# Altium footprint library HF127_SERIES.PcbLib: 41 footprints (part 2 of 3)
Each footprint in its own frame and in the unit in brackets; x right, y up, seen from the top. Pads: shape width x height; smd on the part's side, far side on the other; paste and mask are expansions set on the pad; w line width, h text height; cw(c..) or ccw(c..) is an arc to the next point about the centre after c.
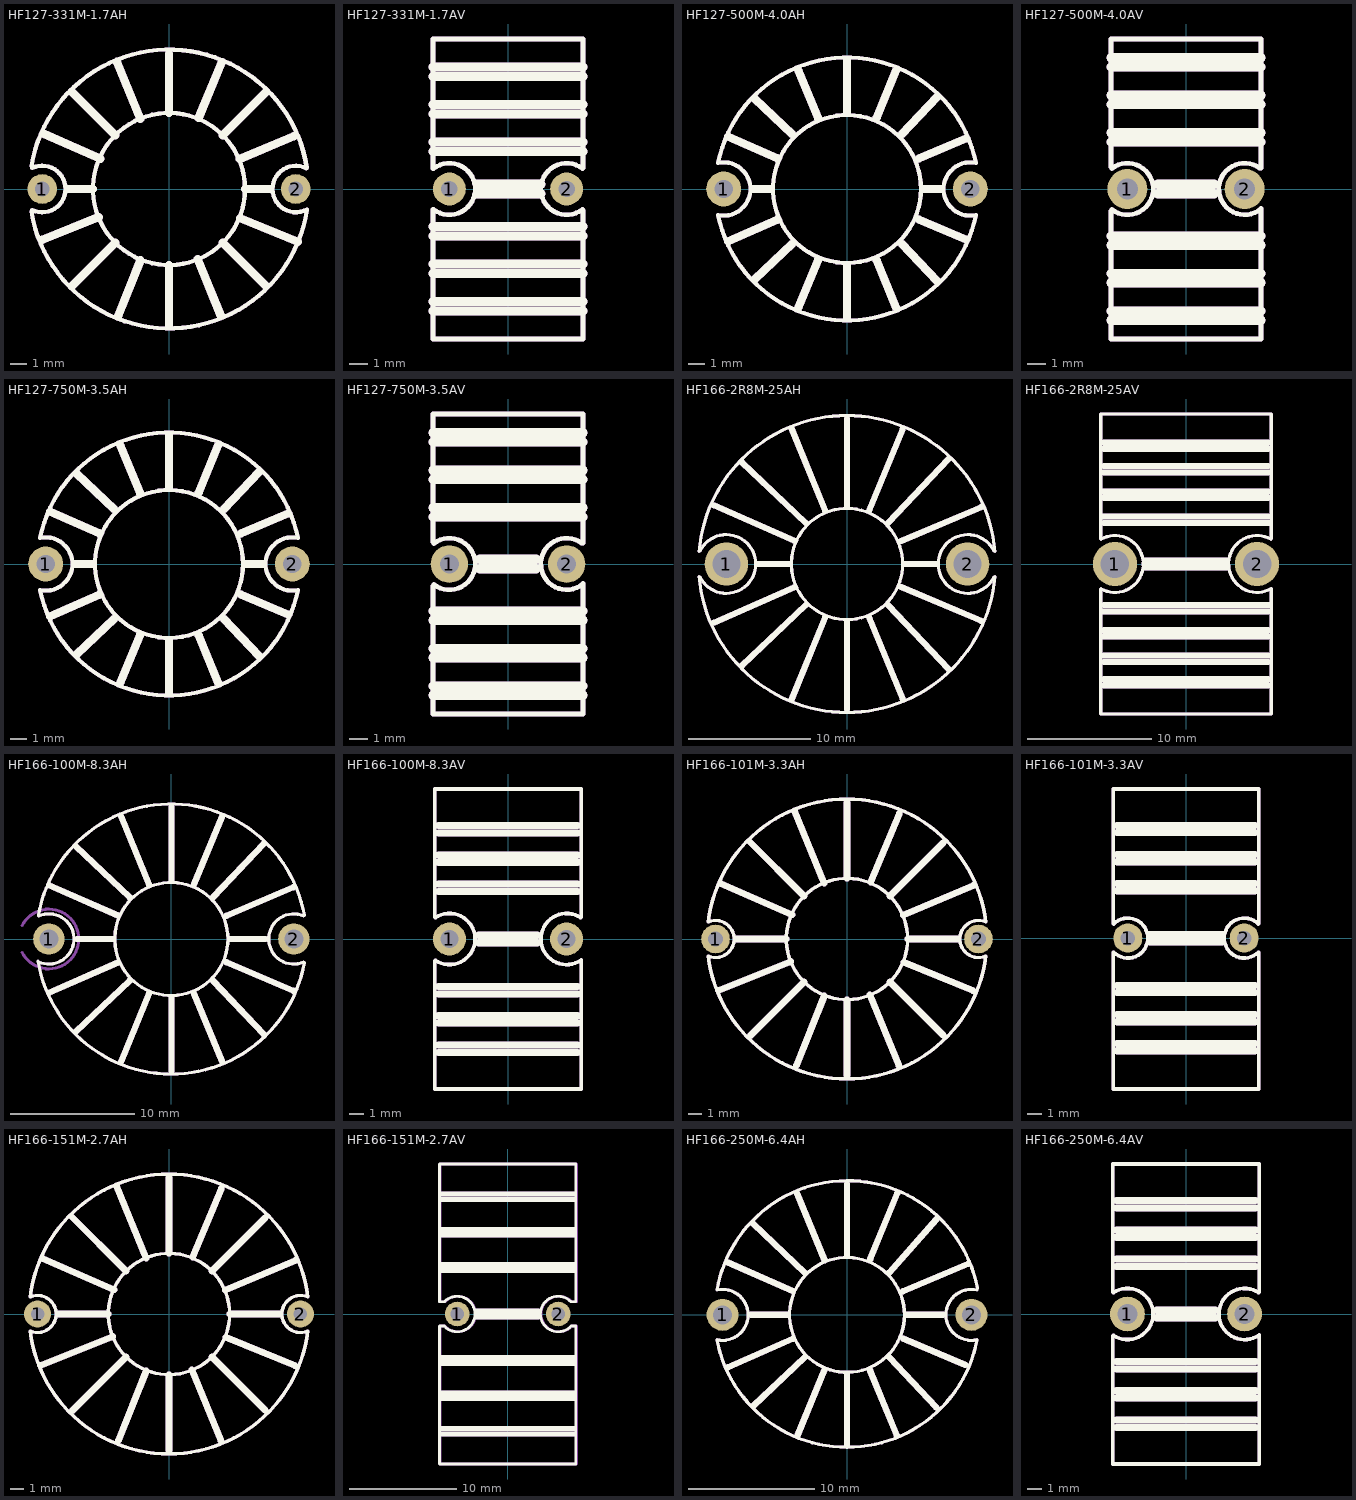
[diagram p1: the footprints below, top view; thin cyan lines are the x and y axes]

## HF127-331M-1.7AH [mil]
pads (2):
  round 70 hole 35: 1(-300,0) 2(300,0)
Top Overlay:
  circle w10: c0,0 r180
  lines w10: -325.63,-53.53 ccw(c0,0) 326.34,-49.02 ; -325.61,53.66 cw(c0,0) 326.16,50.18 ; -323.75,-49.61 ccw(c-300,0) -323.69,49.64 ; 324.6,49.19 ccw(c300,0) 326.03,-48.45
  lines w19.68: -300,-120 -166.38,-66.55 ; -295,130 -162.15,71.46 ; -240,0 -180,0 ; -230,-230 -127.5,-127.5 ; -230,230 -127.5,127.5 ; -122.53,298.96 -67.96,165.83 ; -120,-300 -67.59,-168.97 ; 0,-325 0,-180 ; 0,180 0,320 ; 67.96,-165.83 123.25,-300.72 ; 69.97,167.93 125,300 ; 127.5,-127.5 227.5,-227.5 ; 127.5,127.5 230,230 ; 167.47,70.96 295,125 ; 168.36,-69 305,-125 ; 180,0 240,0
Mechanical 29:
  circle w10: c0,0 r180
  lines w10: -325.63,-53.53 ccw(c0,0) 326.34,-49.02 ; -325.61,53.66 cw(c0,0) 326.16,50.18 ; -323.75,-49.61 ccw(c-300,0) -323.69,49.64 ; 324.6,49.19 ccw(c300,0) 326.03,-48.45
  lines w19.68: -300,-120 -166.38,-66.55 ; -295,130 -162.15,71.46 ; -240,0 -180,0 ; -230,-230 -127.5,-127.5 ; -230,230 -127.5,127.5 ; -122.53,298.96 -67.96,165.83 ; -120,-300 -67.59,-168.97 ; 0,-325 0,-180 ; 0,180 0,320 ; 67.96,-165.83 123.25,-300.72 ; 69.97,167.93 125,300 ; 127.5,-127.5 227.5,-227.5 ; 127.5,127.5 230,230 ; 167.47,70.96 295,125 ; 168.36,-69 305,-125 ; 180,0 240,0
  text "'.Designator'" at -1750,-64.85 h400

## HF127-331M-1.7AV [mil]
pads (2):
  round 70 hole 35: 1(-125,0) 2(125,0)
Top Overlay:
  lines w10: -160,-43.44 -160,-320 -90,-320 -30,-320 30,-320 70,-320 160,-320 160,-140 160,-45 ; -160,43.44 -160,255 -160,320 160,320 160,180 160,45 ; -158.74,-43.44 ccw(c-125,0) -158.74,43.44 ; 158.77,-43.41 cw(c125,0) 158.77,43.41
  lines w19.68: -160,-260 160,-260 ; -160,-240 160,-240 ; -160,-180 160,-180 ; -160,-160 160,-160 ; -160,-100 160,-100 ; -160,-80 160,-80 ; -160,80 160,80 ; -160,100 160,100 ; -160,160 160,160 ; -160,180 160,180 ; -160,240 160,240 ; -160,260 160,260 ; -65,-10 70,-10 ; -65,10 70,10
Mechanical 29:
  lines w10: -160,-43.44 -160,-320 -90,-320 -30,-320 30,-320 70,-320 160,-320 160,-140 160,-45 ; -160,43.44 -160,255 -160,320 160,320 160,180 160,45 ; -158.74,-43.44 ccw(c-125,0) -158.74,43.44 ; 158.77,-43.41 cw(c125,0) 158.77,43.41
  lines w19.68: -160,-260 160,-260 ; -160,-240 160,-240 ; -160,-180 160,-180 ; -160,-160 160,-160 ; -160,-100 160,-100 ; -160,-80 160,-80 ; -160,80 160,80 ; -160,100 160,100 ; -160,160 160,160 ; -160,180 160,180 ; -160,240 160,240 ; -160,260 160,260 ; -65,-10 70,-10 ; -65,10 70,10
  text "'.Designator'" at -1750,-64.85 h400

## HF127-500M-4.0AH [mil]
pads (2):
  round 85 hole 45: 1(-300,0) 2(300,0)
Top Overlay:
  circle w10: c0,0 r180
  lines w10: -313.62,-63.56 ccw(c0,0) 313.62,-63.56 cw(c300,0) 313.62,63.56 ccw(c0,0) -313.62,63.56 cw(c-300,0) -313.62,-63.56
  lines w19.68: -288.97,-127.34 -170.03,-74.93 ; -288.97,127.34 -170.03,74.93 ; -230,0 -185,0 ; -225,-220 -132.7,-132.43 ; -225,220 -132.7,132.43 ; -118.3,-288.65 -70.44,-171.87 ; -118.3,288.65 -70.44,171.87 ; 0,-315 0,-185 ; 0,185 0,315 ; 72.46,-173.99 120,-290 ; 72.46,173.99 120,290 ; 132.5,-132.5 220,-225 ; 132.5,132.5 220,225 ; 175.3,-74.28 290.76,-123.2 ; 175.3,74.28 290.76,123.2 ; 185,0 230,0
Mechanical 29:
  circle w10: c0,0 r180
  lines w10: -313.62,-63.56 ccw(c0,0) 313.62,-63.56 cw(c300,0) 313.62,63.56 ccw(c0,0) -313.62,63.56 cw(c-300,0) -313.62,-63.56
  lines w19.68: -288.97,-127.34 -170.03,-74.93 ; -288.97,127.34 -170.03,74.93 ; -230,0 -185,0 ; -225,-220 -132.7,-132.43 ; -225,220 -132.7,132.43 ; -118.3,-288.65 -70.44,-171.87 ; -118.3,288.65 -70.44,171.87 ; 0,-315 0,-185 ; 0,185 0,315 ; 72.46,-173.99 120,-290 ; 72.46,173.99 120,290 ; 132.5,-132.5 220,-225 ; 132.5,132.5 220,225 ; 175.3,-74.28 290.76,-123.2 ; 175.3,74.28 290.76,123.2 ; 185,0 230,0
  text "'.Designator'" at -1750,-64.85 h400

## HF127-500M-4.0AV [mil]
pads (2):
  round 85 hole 45: 1(-125,0) 2(125,0)
Top Overlay:
  lines w10: -160,-46.35 -160,-320 -90,-320 -30,-320 30,-320 70,-320 160,-320 160,-140 160,-41.39 ; -160,46.35 -160,255 -160,320 160,320 160,180 160,44 ; -158.15,-43.89 ccw(c-125,0) -158.15,43.89 ; 158,44 ccw(c125,0) 160,-42.43
  lines w19.68: -160,-280 160,-280 ; -160,-260 160,-260 ; -160,-200 160,-200 ; -160,-180 160,-180 ; -160,-120 160,-120 ; -160,-100 160,-100 ; -160,100 160,100 ; -160,120 160,120 ; -160,180 160,180 ; -160,200 160,200 ; -160,260 160,260 ; -160,280 160,280 ; -60,-10 60,-10 ; -60,10 60,10
Mechanical 29:
  lines w10: -160,-46.35 -160,-320 -90,-320 -30,-320 30,-320 70,-320 160,-320 160,-140 160,-41.39 ; -160,46.35 -160,255 -160,320 160,320 160,180 160,44 ; -158.15,-43.89 ccw(c-125,0) -158.15,43.89 ; 158,44 ccw(c125,0) 160,-42.43
  lines w19.68: -160,-280 160,-280 ; -160,-260 160,-260 ; -160,-200 160,-200 ; -160,-180 160,-180 ; -160,-120 160,-120 ; -160,-100 160,-100 ; -160,100 160,100 ; -160,120 160,120 ; -160,180 160,180 ; -160,200 160,200 ; -160,260 160,260 ; -160,280 160,280 ; -60,-10 60,-10 ; -60,10 60,10
  text "'.Designator'" at -1750,-64.85 h400

## HF127-750M-3.5AH [mil]
pads (2):
  round 85 hole 45: 1(-300,0) 2(300,0)
Top Overlay:
  circle w10: c0,0 r180
  lines w10: -313.62,-63.56 ccw(c0,0) 313.62,-63.56 cw(c300,0) 313.62,63.56 ccw(c0,0) -313.62,63.56 cw(c-300,0) -313.62,-63.56
  lines w19.68: -288.97,-127.34 -170.03,-74.93 ; -288.97,127.34 -170.03,74.93 ; -230,0 -185,0 ; -225,-220 -132.7,-132.43 ; -225,220 -132.7,132.43 ; -118.3,-288.65 -70.44,-171.87 ; -118.3,288.65 -70.44,171.87 ; 0,-315 0,-185 ; 0,185 0,315 ; 72.46,-173.99 120,-290 ; 72.46,173.99 120,290 ; 132.5,-132.5 220,-225 ; 132.5,132.5 220,225 ; 175.3,-74.28 290.76,-123.2 ; 175.3,74.28 290.76,123.2 ; 185,0 230,0
Mechanical 29:
  circle w10: c0,0 r180
  lines w10: -313.62,-63.56 ccw(c0,0) 313.62,-63.56 cw(c300,0) 313.62,63.56 ccw(c0,0) -313.62,63.56 cw(c-300,0) -313.62,-63.56
  lines w19.68: -288.97,-127.34 -170.03,-74.93 ; -288.97,127.34 -170.03,74.93 ; -230,0 -185,0 ; -225,-220 -132.7,-132.43 ; -225,220 -132.7,132.43 ; -118.3,-288.65 -70.44,-171.87 ; -118.3,288.65 -70.44,171.87 ; 0,-315 0,-185 ; 0,185 0,315 ; 72.46,-173.99 120,-290 ; 72.46,173.99 120,290 ; 132.5,-132.5 220,-225 ; 132.5,132.5 220,225 ; 175.3,-74.28 290.76,-123.2 ; 175.3,74.28 290.76,123.2 ; 185,0 230,0
  text "'.Designator'" at -1750,-64.85 h400

## HF127-750M-3.5AV [mil]
pads (2):
  round 80 hole 40: 1(-125,0) 2(125,0)
Top Overlay:
  lines w10: -160,-46.35 -160,-320 -90,-320 -30,-320 30,-320 70,-320 160,-320 160,-140 160,-41.39 ; -160,46.35 -160,255 -160,320 160,320 160,180 160,44 ; -158.15,-43.89 ccw(c-125,0) -158.15,43.89 ; 158,44 ccw(c125,0) 160,-42.43
  lines w19.68: -160,-280 160,-280 ; -160,-260 160,-260 ; -160,-200 160,-200 ; -160,-180 160,-180 ; -160,-120 160,-120 ; -160,-100 160,-100 ; -160,100 160,100 ; -160,120 160,120 ; -160,180 160,180 ; -160,200 160,200 ; -160,260 160,260 ; -160,280 160,280 ; -60,-10 60,-10 ; -60,10 60,10
Mechanical 29:
  lines w10: -160,-46.35 -160,-320 -90,-320 -30,-320 30,-320 70,-320 160,-320 160,-140 160,-41.39 ; -160,46.35 -160,255 -160,320 160,320 160,180 160,44 ; -158.15,-43.89 ccw(c-125,0) -158.15,43.89 ; 158,44 ccw(c125,0) 160,-42.43
  lines w19.68: -160,-280 160,-280 ; -160,-260 160,-260 ; -160,-200 160,-200 ; -160,-180 160,-180 ; -160,-120 160,-120 ; -160,-100 160,-100 ; -160,100 160,100 ; -160,120 160,120 ; -160,180 160,180 ; -160,200 160,200 ; -160,260 160,260 ; -160,280 160,280 ; -60,-10 60,-10 ; -60,10 60,10
  text "'.Designator'" at -1750,-64.85 h400

## HF166-2R8M-25AH [mil]
pads (2):
  round 140 hole 90: 1(-390,0) 2(390,0)
Top Overlay:
  circle w10: c0,0 r180
  lines w10: -478.34,-39.86 ccw(c0,0) 478.27,-40.7 ; -478.34,39.86 cw(c0,0) 478.34,39.86 ; -474.97,-42.49 ccw(c-390,0) -474.97,42.49 ; 474.97,-42.49 cw(c390,0) 474.97,42.49
  lines w19.68: -430.19,-189.57 -170.03,-74.93 ; -430.19,189.57 -170.03,74.93 ; -340.45,-329.53 -132.7,-132.43 ; -340.45,329.53 -132.7,132.43 ; -290,0 -185,0 ; -179.65,-438.34 -70.44,-171.87 ; -179.65,438.34 -70.44,171.87 ; 0,-470 0,-185 ; 0,185 0,470 ; 72.46,-173.99 179.83,-435.97 ; 72.46,173.99 179.83,435.97 ; 132.5,-132.5 329.36,-340.61 ; 132.5,132.5 329.36,340.61 ; 175.3,-74.28 434.09,-183.94 ; 175.3,74.28 434.09,183.94 ; 185,0 290,0
Mechanical 29:
  circle w10: c0,0 r180
  lines w10: -478.34,-39.86 ccw(c0,0) 478.27,-40.7 ; -478.34,39.86 cw(c0,0) 478.34,39.86 ; -474.97,-42.49 ccw(c-390,0) -474.97,42.49 ; 474.97,-42.49 cw(c390,0) 474.97,42.49
  lines w19.68: -430.19,-189.57 -170.03,-74.93 ; -430.19,189.57 -170.03,74.93 ; -340.45,-329.53 -132.7,-132.43 ; -340.45,329.53 -132.7,132.43 ; -290,0 -185,0 ; -179.65,-438.34 -70.44,-171.87 ; -179.65,438.34 -70.44,171.87 ; 0,-470 0,-185 ; 0,185 0,470 ; 72.46,-173.99 179.83,-435.97 ; 72.46,173.99 179.83,435.97 ; 132.5,-132.5 329.36,-340.61 ; 132.5,132.5 329.36,340.61 ; 175.3,-74.28 434.09,-183.94 ; 175.3,74.28 434.09,183.94 ; 185,0 290,0
  text "'.Designator'" at -1750,-64.85 h400

## HF166-2R8M-25AV [mil]
pads (2):
  round 140 hole 90: 1(-225,0) 2(225,0)
Top Overlay:
  lines w10: -270,-80 -270,-475 265,-475 ; -270,80 -270,475 270,475 270,80.5 ; -269.12,-78.44 ccw(c-225,0) -269.12,78.44 ; 268.92,78.56 ccw(c225,0) 270,-77.94 270,-475
  lines w19.68: -265,-230 260,-230 ; -265,-150 260,-150 ; -265,150 260,150 ; -265,230 260,230 ; -260,-385 260,-385 ; -260,-365 260,-365 ; -260,-310 260,-310 ; -260,-290 260,-290 ; -260,-210 260,-210 ; -260,-130 265,-130 ; -260,130 265,130 ; -260,210 260,210 ; -260,290 260,290 ; -260,310 260,310 ; -260,365 260,365 ; -260,385 260,385 ; -130,-10 130,-10 ; -130,10 130,10
Mechanical 29:
  lines w10: -270,-80 -270,-475 265,-475 ; -270,80 -270,475 270,475 270,80.5 ; -269.12,-78.44 ccw(c-225,0) -269.12,78.44 ; 268.92,78.56 ccw(c225,0) 270,-77.94 270,-475
  lines w19.68: -265,-230 260,-230 ; -265,-150 260,-150 ; -265,150 260,150 ; -265,230 260,230 ; -260,-385 260,-385 ; -260,-365 260,-365 ; -260,-310 260,-310 ; -260,-290 260,-290 ; -260,-210 260,-210 ; -260,-130 265,-130 ; -260,130 265,130 ; -260,210 260,210 ; -260,290 260,290 ; -260,310 260,310 ; -260,365 260,365 ; -260,385 260,385 ; -130,-10 130,-10 ; -130,10 130,10
  text "'.Designator'" at -1750,-64.85 h400

## HF166-100M-8.3AH [mil]
pads (2):
  round 100 hole 60: 1(-390,0) 2(390,0)
Top Overlay:
  circle w10: c0,0 r180
  lines w10: -424.15,-70.69 ccw(c0,0) 423.54,-74.28 ; -423.85,-72.49 ccw(c-390,0) -422.48,73.11 ; -423.38,75.15 cw(c0,0) 423.54,74.28 ; 420.86,-73.81 cw(c390,0) 420.86,73.81
  lines w19.68: -389.31,-171.56 -170.03,-74.93 ; -389.31,171.56 -170.03,74.93 ; -304.69,-295.6 -132.7,-132.43 ; -304.69,295.6 -132.7,132.43 ; -300,0 -185,0 ; -159.86,-390.06 -70.44,-171.87 ; -159.86,390.06 -70.44,171.87 ; 0,-420 0,-185 ; 0,185 0,420 ; 72.46,-173.99 160.84,-389.65 ; 72.46,173.99 160.84,389.65 ; 132.5,-132.5 295.22,-304.52 ; 132.5,132.5 295.22,304.52 ; 175.3,-74.28 388.11,-164.45 ; 175.3,74.28 388.11,164.45 ; 185,0 300,0
Mechanical 29:
  circle w10: c0,0 r180
  lines w10: -474.97,-42.49 ccw(c-390,0) -474.97,42.49 ; -424.15,-70.69 ccw(c0,0) 423.54,-74.28 ; -423.85,-72.49 ccw(c-390,0) -422.48,73.11 ; -423.38,75.15 cw(c0,0) 423.54,74.28 ; 420.86,-73.81 cw(c390,0) 420.86,73.81
  lines w19.68: -389.31,-171.56 -170.03,-74.93 ; -389.31,171.56 -170.03,74.93 ; -304.69,-295.6 -132.7,-132.43 ; -304.69,295.6 -132.7,132.43 ; -300,0 -185,0 ; -159.86,-390.06 -70.44,-171.87 ; -159.86,390.06 -70.44,171.87 ; 0,-420 0,-185 ; 0,185 0,420 ; 72.46,-173.99 160.84,-389.65 ; 72.46,173.99 160.84,389.65 ; 132.5,-132.5 295.22,-304.52 ; 132.5,132.5 295.22,304.52 ; 175.3,-74.28 388.11,-164.45 ; 175.3,74.28 388.11,164.45 ; 185,0 300,0
  text "'.Designator'" at -1750,-64.85 h400

## HF166-100M-8.3AV [mil]
pads (2):
  round 90 hole 50: 1(-160,0) 2(160,0)
Top Overlay:
  lines w10: -200,-60 -200,-410 200,-410 200,-57.45 cw(c160,0) 198.83,58.24 ; -200,60 -200,410 200,410 200,60 ; -198.83,-58.24 ccw(c-160,0) -198.83,58.24
  lines w19.68: -190,-310 190,-310 ; -190,-290 190,-290 ; -190,-230 190,-230 ; -190,-210 190,-210 ; -190,-150 190,-150 ; -190,-130 190,-130 ; -190,130 190,130 ; -190,150 190,150 ; -190,210 190,210 ; -190,230 190,230 ; -190,290 190,290 ; -190,310 190,310 ; -80,-10 80,-10 ; -80,10 80,10
Mechanical 29:
  lines w10: -200,-60 -200,-410 200,-410 200,-57.45 cw(c160,0) 198.83,58.24 ; -200,60 -200,410 200,410 200,60 ; -198.83,-58.24 ccw(c-160,0) -198.83,58.24
  lines w19.68: -190,-310 190,-310 ; -190,-290 190,-290 ; -190,-230 190,-230 ; -190,-210 190,-210 ; -190,-150 190,-150 ; -190,-130 190,-130 ; -190,130 190,130 ; -190,150 190,150 ; -190,210 190,210 ; -190,230 190,230 ; -190,290 190,290 ; -190,310 190,310 ; -80,-10 80,-10 ; -80,10 80,10
  text "'.Designator'" at -1750,-64.85 h400

## HF166-101M-3.3AH [mil]
pads (2):
  round 85 hole 45: 1(-390,0) 2(390,0)
Top Overlay:
  circle w10: c0,0 r180
  lines w10: -411.83,-51.16 ccw(c0,0) 411.83,-51.16 ; -411.83,51.16 cw(c0,0) 411.85,51 ; -410.57,-51.01 ccw(c-390,0) -410.57,51.01 ; 410.57,-51.01 cw(c390,0) 410.88,50.88
  lines w19.68: -381.03,-152.41 -166.38,-66.55 ; -374.91,165.21 -162.15,71.46 ; -330,0 -180,0 ; -290,290 -127.5,127.5 ; -287.5,-287.5 -127.5,-127.5 ; -155.63,379.74 -67.96,165.83 ; -150,-375 -67.59,-168.97 ; 0,-405 0,-180 ; 0,180 0,405 ; 67.96,-165.83 153.88,-375.46 ; 69.97,167.93 155.33,372.78 ; 127.5,-127.5 285,-285 ; 127.5,127.5 285,285 ; 167.47,70.96 375.4,159.07 ; 168.36,-69 373.71,-153.16 ; 180,0 330,0
Mechanical 29:
  circle w10: c0,0 r180
  lines w10: -411.83,-51.16 ccw(c0,0) 411.83,-51.16 ; -411.83,51.16 cw(c0,0) 411.85,51 ; -410.57,-51.01 ccw(c-390,0) -410.57,51.01 ; 410.57,-51.01 cw(c390,0) 410.88,50.88
  lines w19.68: -381.03,-152.41 -166.38,-66.55 ; -374.91,165.21 -162.15,71.46 ; -330,0 -180,0 ; -290,290 -127.5,127.5 ; -287.5,-287.5 -127.5,-127.5 ; -155.63,379.74 -67.96,165.83 ; -150,-375 -67.59,-168.97 ; 0,-405 0,-180 ; 0,180 0,405 ; 67.96,-165.83 153.88,-375.46 ; 69.97,167.93 155.33,372.78 ; 127.5,-127.5 285,-285 ; 127.5,127.5 285,285 ; 167.47,70.96 375.4,159.07 ; 168.36,-69 373.71,-153.16 ; 180,0 330,0
  text "'.Designator'" at -1750,-64.85 h400

## HF166-101M-3.3AV  [mil]
pads (2):
  round 80 hole 40: 1(-160,0) 2(160,0)
Top Overlay:
  lines w10: -200,-39 -200,-415 200,-415 200,-39 ; -200,39 -200,410 200,410 200,39 ; -198.89,-38.89 ccw(c-160,0) -198.89,38.89 ; 198.89,-38.89 cw(c160,0) 198.89,38.89
  lines w19.68: -190,-310 190,-310 ; -190,-290 190,-290 ; -190,-230 190,-230 ; -190,-210 190,-210 ; -190,-150 190,-150 ; -190,-130 190,-130 ; -190,130 190,130 ; -190,150 190,150 ; -190,210 190,210 ; -190,230 190,230 ; -190,290 190,290 ; -190,310 190,310 ; -100,-10 100,-10 ; -100,10 100,10
Mechanical 29:
  lines w10: -200,-39 -200,-415 200,-415 200,-39 ; -200,39 -200,410 200,410 200,39 ; -198.89,-38.89 ccw(c-160,0) -198.89,38.89 ; 198.89,-38.89 cw(c160,0) 198.89,38.89
  lines w19.68: -190,-310 190,-310 ; -190,-290 190,-290 ; -190,-230 190,-230 ; -190,-210 190,-210 ; -190,-150 190,-150 ; -190,-130 190,-130 ; -190,130 190,130 ; -190,150 190,150 ; -190,210 190,210 ; -190,230 190,230 ; -190,290 190,290 ; -190,310 190,310 ; -100,-10 100,-10 ; -100,10 100,10
  text "'.Designator'" at -1750,-64.85 h400

## HF166-151M-2.7AH [mil]
pads (2):
  round 80 hole 40: 1(-390,0) 2(390,0)
Top Overlay:
  circle w10: c0,0 r180
  lines w10: -411.83,-51.16 ccw(c0,0) 411.83,-51.16 ; -411.83,51.16 cw(c0,0) 411.85,51 ; -410.57,-51.01 ccw(c-390,0) -410.57,51.01 ; 410.57,-51.01 cw(c390,0) 410.88,50.88
  lines w19.68: -381.03,-152.41 -166.38,-66.55 ; -374.91,165.21 -162.15,71.46 ; -330,0 -180,0 ; -290,290 -127.5,127.5 ; -287.5,-287.5 -127.5,-127.5 ; -155.63,379.74 -67.96,165.83 ; -150,-375 -67.59,-168.97 ; 0,-405 0,-180 ; 0,180 0,405 ; 67.96,-165.83 153.88,-375.46 ; 69.97,167.93 155.33,372.78 ; 127.5,-127.5 285,-285 ; 127.5,127.5 285,285 ; 167.47,70.96 375.4,159.07 ; 168.36,-69 373.71,-153.16 ; 180,0 330,0
Mechanical 29:
  circle w10: c0,0 r180
  lines w10: -411.83,-51.16 ccw(c0,0) 411.83,-51.16 ; -411.83,51.16 cw(c0,0) 411.85,51 ; -410.57,-51.01 ccw(c-390,0) -410.57,51.01 ; 410.57,-51.01 cw(c390,0) 410.88,50.88
  lines w19.68: -381.03,-152.41 -166.38,-66.55 ; -374.91,165.21 -162.15,71.46 ; -330,0 -180,0 ; -290,290 -127.5,127.5 ; -287.5,-287.5 -127.5,-127.5 ; -155.63,379.74 -67.96,165.83 ; -150,-375 -67.59,-168.97 ; 0,-405 0,-180 ; 0,180 0,405 ; 67.96,-165.83 153.88,-375.46 ; 69.97,167.93 155.33,372.78 ; 127.5,-127.5 285,-285 ; 127.5,127.5 285,285 ; 167.47,70.96 375.4,159.07 ; 168.36,-69 373.71,-153.16 ; 180,0 330,0
  text "'.Designator'" at -1750,-64.85 h400

## HF166-151M-2.7AV [mil]
pads (2):
  round 90 hole 50: 1(-185,0) 2(185,0)
Top Overlay:
  lines w10: -232.32,-44.56 ccw(c-185,0) -231.97,44.93 ; -232.32,-44.19 -250,-44.19 -250,-550 -90,-550 -30,-550 30,-550 70,-550 250,-550 250,-140 250,-45.81 250,-44.19 232.32,-44.19 ; -232.27,45.21 -250,45.21 -250,255 -250,550 245,550 ; 232.32,-44.56 cw(c185,0) 225.61,50.76 232.27,45.21 250,45.21 250,180 250,550
  lines w19.68: -240,-440 240,-440 ; -240,-420 240,-420 ; -240,-310 240,-310 ; -240,-290 240,-290 ; -240,-180 240,-180 ; -240,-160 240,-160 ; -240,160 240,160 ; -240,180 240,180 ; -240,290 240,290 ; -240,310 240,310 ; -240,420 240,420 ; -240,440 240,440 ; -115,-10 110,-10 ; -115,10 110,10
Mechanical 29:
  lines w10: -229.82,-44.56 ccw(c-182.5,0) -229.47,44.93 ; -229.82,-44.19 -247.5,-44.19 -247.5,-550 -87.5,-550 -27.5,-550 32.5,-550 72.5,-550 252.5,-550 252.5,-140 252.5,-45.81 252.5,-44.19 234.82,-44.19 ; -229.77,45.21 -247.5,45.21 -247.5,255 -247.5,550 247.5,550 ; 234.82,-44.56 cw(c187.5,0) 228.11,50.76 234.77,45.21 252.5,45.21 252.5,180 252.5,550
  lines w19.68: -237.5,-440 242.5,-440 ; -237.5,-420 242.5,-420 ; -237.5,-310 242.5,-310 ; -237.5,-290 242.5,-290 ; -237.5,-180 242.5,-180 ; -237.5,-160 242.5,-160 ; -237.5,160 242.5,160 ; -237.5,180 242.5,180 ; -237.5,290 242.5,290 ; -237.5,310 242.5,310 ; -237.5,420 242.5,420 ; -237.5,440 242.5,440 ; -112.5,-10 112.5,-10 ; -112.5,10 112.5,10
  text "'.Designator'" at -1750,-64.85 h400

## HF166-250M-6.4AH [mil]
pads (2):
  round 100 hole 60: 1(-390,0) 2(390,0)
Top Overlay:
  circle w10: c0,0 r180
  lines w10: 407.6,78.04 ccw(c390,0) 407.6,-78.04 cw(c0,0) -407.6,-78.04 ccw(c-390,0) -407.6,78.04 cw(c1.02,5.51) 408.61,83.55
  lines w19.68: -372.56,-164.18 -170.03,-74.93 ; -372.56,164.18 -170.03,74.93 ; -300,0 -185,0 ; -294.16,-285.61 -132.7,-132.43 ; -294.16,285.61 -132.7,132.43 ; -156.35,381.5 -70.44,171.87 ; -154.91,-377.99 -70.44,-171.87 ; 0,-410 0,-185 ; 0,185 0,410 ; 72.46,-173.99 155.9,-377.58 ; 72.46,173.99 157.33,381.09 ; 132.5,-132.5 280,-290 ; 132.5,132.5 280,300 ; 175.3,-74.28 371.16,-157.27 ; 175.3,74.28 380,160 ; 185,0 300,0
Mechanical 29:
  circle w10: c0,0 r180
  lines w10: 407.6,78.04 ccw(c390,0) 407.6,-78.04 cw(c0,0) -407.6,-78.04 ccw(c-390,0) -407.6,78.04 cw(c1.02,5.51) 408.61,83.55
  lines w19.68: -372.56,-164.18 -170.03,-74.93 ; -372.56,164.18 -170.03,74.93 ; -300,0 -185,0 ; -294.16,-285.61 -132.7,-132.43 ; -294.16,285.61 -132.7,132.43 ; -156.35,381.5 -70.44,171.87 ; -154.91,-377.99 -70.44,-171.87 ; 0,-410 0,-185 ; 0,185 0,410 ; 72.46,-173.99 155.9,-377.58 ; 72.46,173.99 157.33,381.09 ; 132.5,-132.5 280,-290 ; 132.5,132.5 280,300 ; 175.3,-74.28 371.16,-157.27 ; 175.3,74.28 380,160 ; 185,0 300,0
  text "'.Designator'" at -1750,-64.85 h400

## HF166-250M-6.4AV [mil]
pads (2):
  round 95 hole 55: 1(-160,0) 2(160,0)
Top Overlay:
  lines w10: -200,-60 -200,-410 200,-410 200,-57.45 cw(c160,0) 198.83,58.24 ; -200,60 -200,410 200,410 200,60 ; -198.83,-58.24 ccw(c-160,0) -198.83,58.24
  lines w19.68: -190,-310 190,-310 ; -190,-290 190,-290 ; -190,-230 190,-230 ; -190,-210 190,-210 ; -190,-150 190,-150 ; -190,-130 190,-130 ; -190,130 190,130 ; -190,150 190,150 ; -190,210 190,210 ; -190,230 190,230 ; -190,290 190,290 ; -190,310 190,310 ; -80,-10 80,-10 ; -80,10 80,10
Mechanical 29:
  lines w10: -200,-60 -200,-410 200,-410 200,-57.45 cw(c160,0) 198.83,58.24 ; -200,60 -200,410 200,410 200,60 ; -198.83,-58.24 ccw(c-160,0) -198.83,58.24
  lines w19.68: -190,-310 190,-310 ; -190,-290 190,-290 ; -190,-230 190,-230 ; -190,-210 190,-210 ; -190,-150 190,-150 ; -190,-130 190,-130 ; -190,130 190,130 ; -190,150 190,150 ; -190,210 190,210 ; -190,230 190,230 ; -190,290 190,290 ; -190,310 190,310 ; -80,-10 80,-10 ; -80,10 80,10
  text "'.Designator'" at -1750,-64.85 h400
